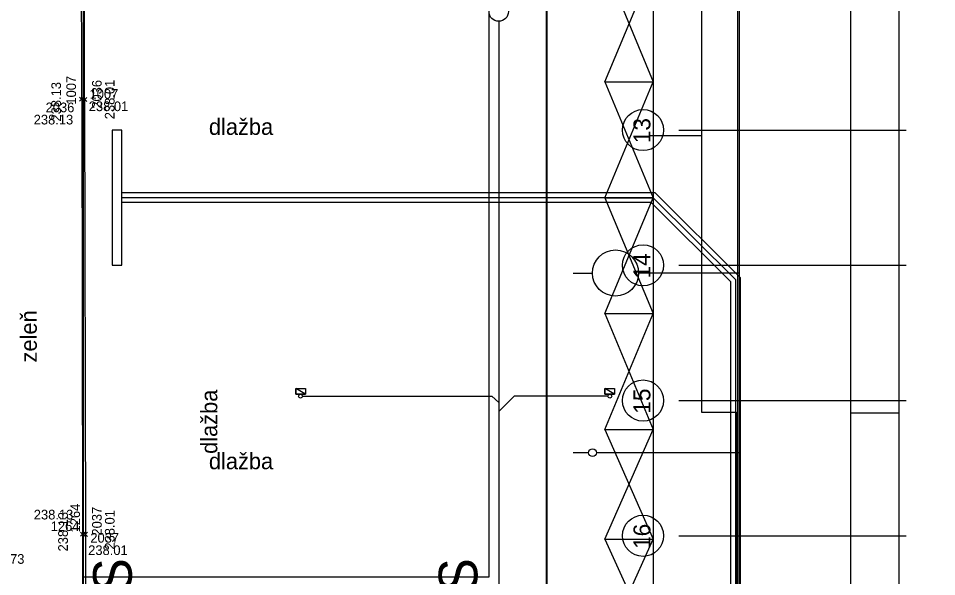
# Model space of a CAD drawing. Extents: x -264205 to -263659, y -1242401 to -1241986.
# Drawn here: x -263951.44 to -263903.94, y -1242184 to -1242155.1 of the extents above; entities that cross this region are included whole.
import ezdxf

# ---------------------------------------------------------------- set-up
doc = ezdxf.new("R2010")
doc.units = 0
for name, color, linetype in [('BOD_CISLO_2-1', 7, 'Continuous'), ('BOD_CISLO_2-3', 7, 'Continuous'), ('BOD_SYMBOL_2-1', 7, 'Continuous'), ('BOD_SYMBOL_2-3', 7, 'Continuous'), ('BOD_VYSKA_2-1', 7, 'Continuous'), ('BOD_VYSKA_2-3', 7, 'Continuous'), ('HESCON_OSI_STAVBY_KFA', 7, 'Continuous'), ('POPIS_2-1', 7, 'Continuous'), ('POPIS_2-3', 7, 'Continuous'), ('PROJEKT_OBRUBNIKY_KOMUNIKACIE', 7, 'Continuous'), ('PROJEKT_TDZ_VODOROVNE', 7, 'Continuous'), ('RAM_NA_TLAC_2-3_1-250', 7, 'Continuous'), ('SITUACIA_DSP_2D', 7, 'Continuous'), ('SO_20-4_OBRUBNIKY_DOLNA_HRANA', 7, 'Continuous'), ('SO_20-4_OBRUBNIKY_HORNA_HRANA', 7, 'Continuous')]:
    doc.layers.add(name, color=color, linetype=linetype)

msp = doc.modelspace()

# ---------------------------------------------------------------- linework, layer by layer
at = {"layer": 'BOD_SYMBOL_2-1'}
for p, q in [((-263948.269, -1242159.393), (-263948.047, -1242159.171)), ((-263948.047, -1242159.393), (-263948.269, -1242159.171)), ((-263948.122, -1242159.41), (-263947.9, -1242159.188)), ((-263947.9, -1242159.41), (-263948.122, -1242159.188)), ((-263948.228, -1242181.91), (-263948.007, -1242181.69)), ((-263948.007, -1242181.91), (-263948.228, -1242181.69)), ((-263948.079, -1242181.917), (-263947.859, -1242181.695)), ((-263947.859, -1242181.917), (-263948.079, -1242181.695))]:
    msp.add_line(p, q, dxfattribs=at)
at = {"layer": 'BOD_SYMBOL_2-3'}
for p, q in [((-263948.047, -1242159.393), (-263948.269, -1242159.171)), ((-263948.047, -1242159.171), (-263948.269, -1242159.393)), ((-263947.9, -1242159.41), (-263948.122, -1242159.188)), ((-263947.9, -1242159.188), (-263948.122, -1242159.41)), ((-263948.007, -1242181.91), (-263948.228, -1242181.69)), ((-263948.007, -1242181.69), (-263948.228, -1242181.91)), ((-263947.859, -1242181.917), (-263948.079, -1242181.695)), ((-263947.859, -1242181.695), (-263948.079, -1242181.917))]:
    msp.add_line(p, q, dxfattribs=at)
at = {"layer": 'HESCON_OSI_STAVBY_KFA'}
for p, q in [((-263908.393, -1242083.237), (-263908.393, -1242246.707)), ((-263917.265, -1242160.882), (-263905.505, -1242160.882)), ((-263917.265, -1242160.882), (-263905.505, -1242160.882)), ((-263917.265, -1242167.882), (-263905.505, -1242167.882)), ((-263917.265, -1242167.882), (-263905.505, -1242167.882)), ((-263917.265, -1242174.882), (-263905.505, -1242174.882)), ((-263917.265, -1242174.882), (-263905.505, -1242174.882)), ((-263917.265, -1242181.882), (-263905.505, -1242181.882)), ((-263917.265, -1242181.882), (-263905.505, -1242181.882))]:
    msp.add_line(p, q, dxfattribs=at)
for centre in [(-263919.125, -1242160.882), (-263919.125, -1242167.882), (-263919.125, -1242174.882), (-263919.125, -1242181.882)]:
    msp.add_circle(centre, 1.064, dxfattribs=at)
at = {"layer": 'PROJEKT_OBRUBNIKY_KOMUNIKACIE'}
msp.add_line((-263948.093, -1242087.901), (-263948.093, -1242241.458), dxfattribs=at)
msp.add_lwpolyline([(-263794.893, -1242227.382), (-263808.968, -1242241.457), (-263894.968, -1242241.457), (-263909.043, -1242227.382), (-263909.043, -1242196.333), (-263914.143, -1242196.333), (-263914.143, -1242132.433), (-263909.043, -1242132.433), (-263909.043, -1242101.382), (-263894.968, -1242087.307), (-263808.968, -1242087.307), (-263794.893, -1242101.382), (-263794.893, -1242227.382)], dxfattribs=at)
at = {"layer": 'PROJEKT_TDZ_VODOROVNE'}
for p, q in [((-263924.088, -1242241.458), (-263924.093, -1242087.307)), ((-263918.593, -1242141.207), (-263918.593, -1242187.557)), ((-263921.093, -1242152.382), (-263918.593, -1242158.382)), ((-263921.093, -1242158.382), (-263918.593, -1242152.382)), ((-263921.093, -1242158.382), (-263918.593, -1242158.382)), ((-263921.093, -1242158.382), (-263918.593, -1242164.382)), ((-263921.093, -1242164.382), (-263918.593, -1242158.382)), ((-263921.093, -1242164.382), (-263918.593, -1242164.382)), ((-263921.093, -1242164.382), (-263918.593, -1242170.382)), ((-263921.093, -1242170.382), (-263918.593, -1242164.382)), ((-263921.093, -1242170.382), (-263918.593, -1242170.382)), ((-263921.093, -1242170.382), (-263918.593, -1242176.382)), ((-263921.093, -1242176.382), (-263918.593, -1242170.382)), ((-263921.093, -1242176.382), (-263918.593, -1242176.382)), ((-263921.093, -1242176.382), (-263918.593, -1242182.062)), ((-263921.093, -1242182.062), (-263918.593, -1242176.382)), ((-263921.093, -1242182.062), (-263918.593, -1242182.062)), ((-263921.093, -1242182.062), (-263918.593, -1242187.557)), ((-263921.093, -1242187.557), (-263918.593, -1242182.062))]:
    msp.add_line(p, q, dxfattribs=at)
msp.add_lwpolyline([(-263927.093, -1242134.007), (-263948.093, -1242134.007), (-263948.093, -1242184.007), (-263927.093, -1242184.007), (-263927.093, -1242134.007)], dxfattribs=at)
at = {"layer": 'RAM_NA_TLAC_2-3_1-250'}
msp.add_line((-263908.389, -1242175.511), (-263905.889, -1242175.511), dxfattribs=at)
msp.add_lwpolyline([(-263980.139, -1242275.511), (-263980.139, -1241985.511), (-263905.889, -1241985.511), (-263905.889, -1242275.511)], close=True, dxfattribs=at)
at = {"layer": 'SITUACIA_DSP_2D'}
for p, q in [((-263924.143, -1242082.64), (-263924.143, -1242185.14)), ((-263948.093, -1242087.901), (-263948.093, -1242241.458)), ((-263916.093, -1242118.282), (-263916.093, -1242175.482)), ((-263914.218, -1242196.332), (-263914.218, -1242132.432)), ((-263914.143, -1242196.333), (-263914.143, -1242132.433)), ((-263926.593, -1242155.252), (-263926.593, -1242204.252)), ((-263946.093, -1242160.882), (-263946.593, -1242160.882)), ((-263946.593, -1242160.882), (-263946.593, -1242167.882)), ((-263946.093, -1242167.882), (-263946.093, -1242160.882)), ((-263916.093, -1242161.182), (-263918.763, -1242161.182)), ((-263918.489, -1242164.132), (-263946.093, -1242164.132)), ((-263918.593, -1242164.382), (-263946.093, -1242164.382)), ((-263918.593, -1242164.382), (-263914.35, -1242168.625)), ((-263918.489, -1242164.132), (-263914.1, -1242168.521)), ((-263918.696, -1242164.632), (-263946.093, -1242164.632)), ((-263918.696, -1242164.632), (-263914.6, -1242168.728)), ((-263946.593, -1242167.882), (-263946.093, -1242167.882)), ((-263922.745, -1242168.282), (-263921.745, -1242168.282)), ((-263914.143, -1242168.282), (-263919.355, -1242168.282)), ((-263914.6, -1242168.728), (-263914.6, -1242199.693)), ((-263914.35, -1242168.625), (-263914.35, -1242199.59)), ((-263914.1, -1242168.521), (-263914.1, -1242199.486)), ((-263937.093, -1242174.553), (-263937.093, -1242174.263)), ((-263937.093, -1242174.263), (-263936.593, -1242174.263)), ((-263936.593, -1242174.553), (-263937.093, -1242174.263)), ((-263936.593, -1242174.553), (-263937.093, -1242174.263)), ((-263937.093, -1242174.263), (-263937.093, -1242174.553)), ((-263936.593, -1242174.263), (-263936.593, -1242174.553)), ((-263921.093, -1242174.553), (-263921.093, -1242174.263)), ((-263921.093, -1242174.263), (-263920.593, -1242174.263)), ((-263920.593, -1242174.553), (-263921.093, -1242174.263)), ((-263920.593, -1242174.553), (-263921.093, -1242174.263)), ((-263921.093, -1242174.263), (-263921.093, -1242174.553)), ((-263920.593, -1242174.263), (-263920.593, -1242174.553)), ((-263936.593, -1242174.553), (-263937.093, -1242174.553)), ((-263937.093, -1242174.553), (-263936.593, -1242174.553)), ((-263936.743, -1242174.653), (-263926.953, -1242174.653)), ((-263926.953, -1242174.653), (-263926.593, -1242174.978)), ((-263925.798, -1242174.653), (-263926.593, -1242175.448)), ((-263920.944, -1242174.653), (-263925.798, -1242174.653)), ((-263920.593, -1242174.553), (-263921.093, -1242174.553)), ((-263921.093, -1242174.553), (-263920.593, -1242174.553)), ((-263916.093, -1242175.482), (-263914.293, -1242175.482)), ((-263914.293, -1242175.482), (-263914.293, -1242210.482)), ((-263921.938, -1242177.582), (-263922.738, -1242177.582)), ((-263915.293, -1242177.582), (-263921.538, -1242177.582)), ((-263914.143, -1242177.582), (-263915.293, -1242177.582))]:
    msp.add_line(p, q, dxfattribs=at)
for centre, radius in [((-263926.593, -1242154.752), 0.5), ((-263920.55, -1242168.282), 1.195), ((-263936.843, -1242174.653), 0.1), ((-263920.844, -1242174.653), 0.1), ((-263921.738, -1242177.582), 0.2)]:
    msp.add_circle(centre, radius, dxfattribs=at)
at = {"layer": 'SO_20-4_OBRUBNIKY_DOLNA_HRANA'}
for points in [[(-263948.011, -1242159.299), (-263948.021, -1242151.313), (-263948.025, -1242142.312), (-263948.033, -1242134.318), (-263948.04, -1242126.323), (-263948.059, -1242118.324), (-263948.067, -1242110.327), (-263948.076, -1242102.327), (-263948.082, -1242094.331), (-263948.087, -1242087.302)], [(-263948.011, -1242159.299), (-263947.969, -1242181.806), (-263947.945, -1242208.885), (-263947.934, -1242214.486), (-263947.908, -1242241.46)]]:
    msp.add_lwpolyline(points, dxfattribs=at)
at = {"layer": 'SO_20-4_OBRUBNIKY_HORNA_HRANA'}
for points in [[(-263948.158, -1242159.282), (-263948.168, -1242151.296), (-263948.172, -1242142.295), (-263948.18, -1242134.301), (-263948.187, -1242126.306), (-263948.206, -1242118.307), (-263948.214, -1242110.31), (-263948.223, -1242102.31), (-263948.229, -1242094.314), (-263948.234, -1242087.448)], [(-263948.158, -1242159.282), (-263948.117, -1242181.8), (-263948.089, -1242208.869), (-263948.089, -1242214.486), (-263948.06, -1242241.6)]]:
    msp.add_lwpolyline(points, dxfattribs=at)

# ---------------------------------------------------------------- texts
at = {"layer": 'BOD_CISLO_2-1'}
for s, p in [('1007', (-263947.756, -1242159.263)), ('2036', (-263950.03, -1242159.959)), ('1264', (-263949.765, -1242181.638)), ('2037', (-263947.717, -1242182.236))]:
    msp.add_text(s, height=0.5, dxfattribs=at).set_placement(p)
at = {"layer": 'BOD_CISLO_2-3'}
for s, p in [('1007', (-263948.456, -1242159.564)), ('2036', (-263947.13, -1242159.777)), ('1264', (-263948.249, -1242181.709)), ('2037', (-263947.127, -1242181.87))]:
    msp.add_text(s, height=0.5, rotation=90, dxfattribs=at).set_placement(p)
at = {"layer": 'BOD_VYSKA_2-1'}
for s, p in [('238.01', (-263947.798, -1242159.902)), ('238.13', (-263950.646, -1242160.591)), ('238.13', (-263950.641, -1242181.037)), ('238.01', (-263947.828, -1242182.878)), ('238.73', (-263953.171, -1242183.332))]:
    msp.add_text(s, height=0.5, dxfattribs=at).set_placement(p)
at = {"layer": 'BOD_VYSKA_2-3'}
for s, p in [('238.13', (-263949.234, -1242160.44)), ('238.01', (-263946.464, -1242160.321)), ('238.01', (-263946.461, -1242182.597)), ('238.13', (-263948.878, -1242182.693))]:
    msp.add_text(s, height=0.5, rotation=90, dxfattribs=at).set_placement(p)
at = {"layer": 'HESCON_OSI_STAVBY_KFA'}
for s, p in [('13', (-263918.744, -1242161.562)), ('14', (-263918.744, -1242168.562)), ('15', (-263918.744, -1242175.562)), ('16', (-263918.744, -1242182.562))]:
    msp.add_text(s, height=0.875, rotation=90, dxfattribs=at).set_placement(p)
at = {"layer": 'POPIS_2-1'}
for p in [(-263941.583, -1242161.131), (-263941.583, -1242178.438)]:
    msp.add_text('dlažba', height=0.8438, dxfattribs=at).set_placement(p)
at = {"layer": 'POPIS_2-3'}
for s, p in [('zeleň', (-263950.485, -1242172.909)), ('dlažba', (-263941.148, -1242177.643))]:
    msp.add_text(s, height=0.8438, rotation=90, dxfattribs=at).set_placement(p)
at = {"layer": 'PROJEKT_TDZ_VODOROVNE'}
for p in [(-263945.572, -1242188.544), (-263927.694, -1242188.544)]:
    msp.add_text('BUS', height=2, rotation=90, dxfattribs=at).set_placement(p)

doc.saveas('drawing.dxf')
